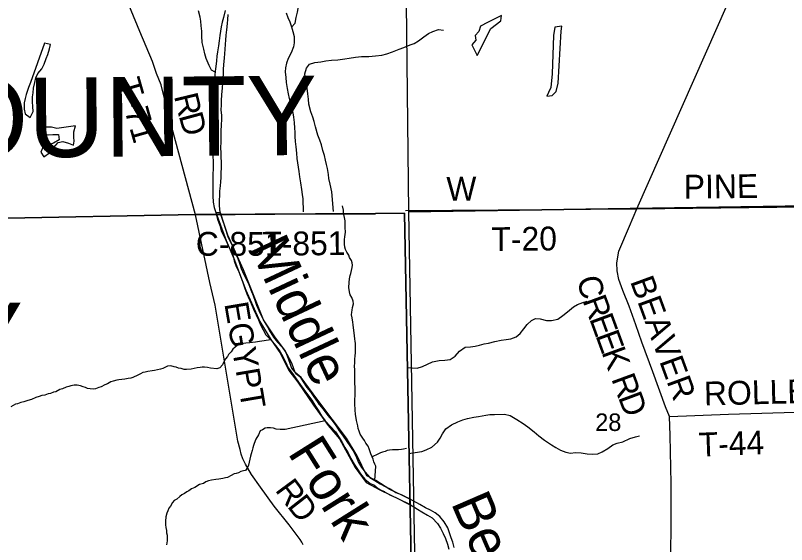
# Model space of a CAD drawing. Extents: x 0 to 34, y 0 to 22.
# Drawn here: x 6.418 to 8.257, y 18.489 to 19.751 of the extents above; entities that cross this region are included whole.
import ezdxf

# ---------------------------------------------------------------- set-up
doc = ezdxf.new("R2010")
doc.units = 0
for name, color, linetype in [('GM_X_County_Road', 7, 'Continuous'), ('GM_X_County_Road_Text', 7, 'Continuous'), ('GM_X_County_Text', 7, 'Continuous'), ('GM_X_Minor_Lake', 7, 'Continuous'), ('GM_X_Minor_River', 7, 'Continuous'), ('GM_X_Minor_River_Text', 7, 'Continuous'), ('GM_X_Rail_Line', 7, 'Continuous'), ('GM_X_Section', 7, 'Continuous'), ('GM_X_Section_Text', 7, 'Continuous'), ('GM_X_Township', 7, 'Continuous'), ('GM_X_Township_Road', 7, 'Continuous'), ('GM_X_Township_Road_Text', 7, 'Continuous'), ('SH_Cut_Line', 7, 'Continuous')]:
    doc.layers.add(name, color=color, linetype=linetype)

msp = doc.modelspace()

# ---------------------------------------------------------------- linework, layer by layer
at = {"layer": 'GM_X_County_Road'}
for p, q in [((6.847, 19.2754), (7.0368, 19.2765)), ((7.0368, 19.2765), (7.2765, 19.2778))]:
    msp.add_line(p, q, dxfattribs=at)
for points in [[(7.8996, 19.2895), (8.1438, 19.8412), (8.341, 20.2911)], [(7.9334, 18.3364), (7.945, 18.3644), (7.9586, 18.3875), (7.9674, 18.4013), (7.9744, 18.4125), (7.9791, 18.424), (7.9807, 18.4411), (7.9811, 18.4735), (7.9819, 18.5282), (7.982, 18.6343), (7.9789, 18.749), (7.9779, 18.7942), (7.9683, 18.8172), (7.9381, 18.901), (7.9119, 18.9716), (7.8977, 19.0131), (7.8816, 19.0572), (7.8668, 19.095), (7.8571, 19.1206), (7.8525, 19.1418), (7.8517, 19.1604), (7.8572, 19.1887), (7.8822, 19.2477), (7.8996, 19.2895)]]:
    msp.add_lwpolyline(points, dxfattribs=at)
at = {"layer": 'GM_X_Minor_Lake'}
for points in [[(7.5194, 19.6553), (7.5513, 19.7196), (7.5757, 19.7379), (7.577, 19.7504), (7.5435, 19.7339), (7.5269, 19.7253), (7.5226, 19.7127), (7.5144, 19.7027), (7.5161, 19.692), (7.5113, 19.6859), (7.506, 19.6805)], [(7.7196, 19.7129), (7.7206, 19.7251), (7.7046, 19.7229), (7.7008, 19.7027), (7.6978, 19.6111), (7.6945, 19.5791), (7.6894, 19.5665), (7.6854, 19.5581), (7.6975, 19.5594), (7.7076, 19.5695), (7.7122, 19.5889)], [(7.7122, 19.5889), (7.7196, 19.7129)], [(6.4541, 19.591), (6.4493, 19.5787), (6.4435, 19.5623), (6.4414, 19.5528), (6.4389, 19.5425), (6.4384, 19.5269), (6.4413, 19.5159), (6.4528, 19.507), (6.4602, 19.5216), (6.4596, 19.5337), (6.4586, 19.5443), (6.4588, 19.5565), (6.4598, 19.566), (6.4608, 19.577), (6.4639, 19.5908), (6.4668, 19.6018), (6.4716, 19.6125), (6.4805, 19.6237), (6.4864, 19.6348), (6.4915, 19.6482), (6.4955, 19.6578), (6.4994, 19.6708), (6.5012, 19.681), (6.4874, 19.6846)], [(6.4874, 19.6846), (6.4541, 19.591)], [(7.506, 19.6805), (7.5194, 19.6553)], [(6.517, 19.4807), (6.5037, 19.4839), (6.4904, 19.4844), (6.4783, 19.4797), (6.4823, 19.468), (6.4968, 19.4659), (6.5074, 19.4669), (6.5203, 19.4671), (6.522, 19.4542), (6.5085, 19.4464), (6.4953, 19.4412), (6.4825, 19.4338), (6.4785, 19.4242), (6.4859, 19.4137), (6.499, 19.4227), (6.5087, 19.4353), (6.5195, 19.4473), (6.5312, 19.4502), (6.5442, 19.4458), (6.5564, 19.4415), (6.5581, 19.451), (6.5568, 19.4605), (6.5574, 19.4734), (6.561, 19.4871)], [(6.561, 19.4871), (6.517, 19.4807)]]:
    msp.add_lwpolyline(points, dxfattribs=at)
at = {"layer": 'GM_X_Minor_River'}
for p, q in [((6.8961, 19.281), (6.9064, 19.281)), ((7.3573, 18.5978), (7.3576, 18.5848))]:
    msp.add_line(p, q, dxfattribs=at)
for points in [[(7.0761, 19.7229), (7.0846, 19.732), (7.0874, 19.7461), (7.0902, 19.7583), (7.093, 19.7721), (7.0951, 19.7839), (7.0968, 19.7972), (7.0977, 19.8067), (7.0987, 19.8185), (7.1, 19.8296), (7.1013, 19.8414), (7.1037, 19.8562), (7.1054, 19.868), (7.1079, 19.8817), (7.1096, 19.8913)], [(6.8942, 19.6155), (6.8852, 19.6205), (6.8801, 19.631), (6.873, 19.648), (6.8698, 19.6594), (6.8669, 19.67), (6.8636, 19.6859), (6.8626, 19.7014), (6.8624, 19.7128), (6.8611, 19.7257), (6.8597, 19.7367), (6.8581, 19.7466), (6.8544, 19.7617)], [(6.9064, 19.281), (6.9043, 19.2975), (6.9048, 19.3093), (6.9054, 19.3218), (6.9056, 19.3317), (6.9069, 19.3439), (6.9079, 19.3538), (6.9085, 19.3644), (6.9087, 19.3751), (6.9096, 19.3876), (6.9094, 19.4017), (6.9088, 19.4115), (6.9086, 19.4214), (6.908, 19.4362), (6.9082, 19.4476), (6.9088, 19.4602), (6.9089, 19.4754), (6.909, 19.4887), (6.9099, 19.5031), (6.9098, 19.5126), (6.9088, 19.5251), (6.909, 19.5377), (6.9096, 19.5479), (6.9105, 19.5616), (6.9114, 19.5784), (6.9123, 19.5894), (6.9129, 19.6008), (6.9138, 19.6118), (6.9144, 19.6221), (6.9146, 19.6339), (6.9162, 19.6491), (6.9172, 19.6601), (6.9178, 19.6697), (6.9191, 19.6818), (6.9197, 19.6921), (6.9203, 19.7039), (6.922, 19.7164), (6.9236, 19.7317), (6.9242, 19.7412), (6.9251, 19.7526)], [(6.9178, 19.7624), (6.9139, 19.7459), (6.911, 19.7345)], [(7.0636, 19.7568), (7.0676, 19.7458), (7.072, 19.7353), (7.076, 19.7232), (7.0796, 19.7126), (7.0824, 19.7005), (7.0823, 19.6853), (7.0809, 19.6758), (7.0755, 19.6616), (7.0685, 19.6482), (7.0645, 19.6371), (7.062, 19.6257), (7.0614, 19.6162), (7.0624, 19.6029), (7.0638, 19.5904), (7.0663, 19.5767), (7.0684, 19.5639), (7.0705, 19.5525), (7.0737, 19.5396), (7.0765, 19.5294), (7.0794, 19.5184), (7.0811, 19.5082), (7.0824, 19.4953), (7.0834, 19.482), (7.084, 19.4722), (7.0841, 19.4623), (7.0851, 19.4498), (7.0864, 19.4373), (7.0878, 19.4225), (7.0892, 19.4092), (7.0905, 19.3993), (7.0918, 19.3891), (7.0935, 19.3785), (7.0956, 19.366), (7.0977, 19.3516), (7.0999, 19.3353), (7.1016, 19.3235), (7.1033, 19.3133), (7.104, 19.2826)], [(6.911, 19.7345), (6.9089, 19.7238), (6.9055, 19.7025), (6.9034, 19.6899), (6.9021, 19.6781), (6.8997, 19.664), (6.8983, 19.6538), (6.897, 19.6423), (6.8957, 19.629), (6.8944, 19.6176), (6.8934, 19.6081), (6.894, 19.5944), (6.8961, 19.5793), (6.896, 19.5644), (6.8958, 19.5549), (6.8953, 19.5397), (6.8951, 19.5257), (6.8942, 19.5116), (6.892, 19.4876), (6.8914, 19.4747), (6.8913, 19.4606), (6.8911, 19.4504), (6.8905, 19.439), (6.8896, 19.4279), (6.889, 19.4139), (6.8896, 19.4032), (6.8891, 19.3858), (6.889, 19.3713), (6.8889, 19.3565), (6.889, 19.3459), (6.8888, 19.3356), (6.8887, 19.3208), (6.8897, 19.3056), (6.8922, 19.2924), (6.8961, 19.281)], [(7.1767, 19.2827), (7.1721, 19.3296), (7.1684, 19.3482), (7.1655, 19.3618), (7.1646, 19.3713), (7.1621, 19.3857), (7.16, 19.3955), (7.1572, 19.4054), (7.1547, 19.4167), (7.1511, 19.4288), (7.1475, 19.4417), (7.1435, 19.453), (7.1391, 19.4651), (7.1338, 19.4852), (7.1306, 19.498), (7.1274, 19.5078), (7.1222, 19.5211), (7.1178, 19.5388), (7.1164, 19.551), (7.1155, 19.5639), (7.1137, 19.5771), (7.112, 19.5881), (7.1099, 19.598), (7.1082, 19.6116), (7.1118, 19.6246), (7.1188, 19.6342), (7.1317, 19.6386), (7.1464, 19.6404), (7.1582, 19.6421), (7.1718, 19.6442), (7.187, 19.6452), (7.2033, 19.6474), (7.2135, 19.6487), (7.229, 19.6508), (7.243, 19.6526), (7.2605, 19.6529), (7.2768, 19.6543), (7.292, 19.6561), (7.3033, 19.6593), (7.3173, 19.6637), (7.3327, 19.67), (7.344, 19.674), (7.3591, 19.6803), (7.3689, 19.6839), (7.3791, 19.6902), (7.3915, 19.6999), (7.4031, 19.7073), (7.4129, 19.7124), (7.4272, 19.7172), (7.4386, 19.7158)], [(7.2753, 18.6418), (7.2771, 18.6754), (7.2751, 18.6803), (7.2723, 18.6863), (7.271, 18.6924), (7.269, 18.6977), (7.2658, 18.7052), (7.2634, 18.712), (7.2618, 18.7173), (7.259, 18.7233), (7.2532, 18.7308), (7.25, 18.7372), (7.2461, 18.7421), (7.2434, 18.7469), (7.2403, 18.7518), (7.2375, 18.759), (7.2354, 18.7654), (7.2342, 18.7715), (7.2325, 18.7779), (7.2316, 18.7847), (7.2286, 18.7999), (7.2277, 18.8094), (7.2274, 18.8253), (7.2276, 18.8303), (7.2275, 18.8356), (7.2277, 18.8432), (7.2283, 18.852), (7.2282, 18.8581), (7.2281, 18.8634), (7.2275, 18.874), (7.2274, 18.8797), (7.2269, 18.8847), (7.2271, 18.89), (7.2274, 18.8984), (7.2272, 18.9048), (7.2266, 18.9151), (7.2269, 18.9215), (7.2274, 18.9318), (7.228, 18.9379), (7.2286, 18.9467), (7.2288, 18.9554), (7.2285, 18.9684), (7.2281, 18.9737), (7.2272, 18.9786), (7.2266, 18.9877), (7.2249, 18.9995), (7.2231, 19.0124), (7.2226, 19.0188), (7.2208, 19.0298), (7.2196, 19.0363), (7.2198, 19.0431), (7.2208, 19.0481), (7.2218, 19.0542), (7.2243, 19.0626), (7.2234, 19.0694), (7.2198, 19.0777), (7.2163, 19.0845), (7.2142, 19.0913), (7.2133, 19.1019), (7.2138, 19.1141), (7.2147, 19.1221), (7.2165, 19.1301), (7.2179, 19.1351), (7.221, 19.1496), (7.2216, 19.1554), (7.2211, 19.1607), (7.2191, 19.166), (7.2148, 19.1735), (7.2128, 19.1788), (7.2085, 19.1859), (7.2053, 19.1927), (7.2037, 19.198), (7.2024, 19.2055), (7.2029, 19.2166), (7.2035, 19.2227), (7.2046, 19.228), (7.2048, 19.2334), (7.2046, 19.2451), (7.2041, 19.2508), (7.2044, 19.2558), (7.2039, 19.2607), (7.203, 19.2687), (7.2005, 19.2789), (7.1999, 19.2861), (7.1982, 19.2964)], [(6.8961, 19.281), (6.9004, 19.2621), (6.9051, 19.2493), (6.9087, 19.2372), (6.9134, 19.2274), (6.9197, 19.215), (6.9252, 19.2022), (6.9311, 19.1897), (6.937, 19.1765), (6.9394, 19.1652), (6.9446, 19.1516), (6.9505, 19.1388), (6.9556, 19.1267), (6.9604, 19.1135), (6.9647, 19.0995), (6.9695, 19.0867), (6.9797, 19.0637), (6.986, 19.0501), (6.9919, 19.0366), (6.9978, 19.0245), (7.0025, 19.0128), (7.0084, 19.0008), (7.0154, 18.9887), (7.0266, 18.9771), (7.039, 18.9625), (7.0483, 18.9498), (7.0553, 18.937), (7.0624, 18.9227), (7.0679, 18.9106), (7.0783, 18.8967), (7.0876, 18.8836), (7.0973, 18.8708), (7.1058, 18.8588), (7.1147, 18.8464), (7.1244, 18.8333), (7.1315, 18.8213), (7.1396, 18.8093), (7.1474, 18.7957), (7.1567, 18.7841), (7.181, 18.7575), (7.1899, 18.7444), (7.1973, 18.732), (7.2032, 18.7199), (7.211, 18.7075), (7.218, 18.6936), (7.2254, 18.6808), (7.2336, 18.6684), (7.241, 18.6575), (7.251, 18.6444), (7.2637, 18.6347), (7.2729, 18.6312)], [(6.8961, 19.281), (6.9202, 19.2136), (6.939, 19.1708), (6.967, 19.0958), (7.0004, 19.0208), (7.0272, 18.9779), (7.0499, 18.9444), (7.07, 18.9042), (7.0914, 18.8761), (7.1288, 18.8212), (7.1636, 18.773), (7.1904, 18.7408), (7.2278, 18.6725), (7.2546, 18.6364), (7.2867, 18.6189), (7.3576, 18.5848)], [(6.9064, 19.281), (6.9137, 19.2559), (6.9173, 19.2457), (6.9249, 19.2208), (6.9378, 19.1959), (6.9422, 19.1834), (6.9481, 19.171), (6.9524, 19.1601), (6.9564, 19.1472), (6.9619, 19.1348), (6.9682, 19.1216), (6.9741, 19.1088), (6.9796, 19.0964), (6.9847, 19.0831), (6.9895, 19.0696), (6.9931, 19.0597), (6.9986, 19.0469), (7.0049, 19.0337), (7.0107, 19.0205), (7.0189, 19.0078), (7.0252, 18.9957), (7.0333, 18.9837), (7.0426, 18.9717), (7.0538, 18.9594), (7.0631, 18.947), (7.0683, 18.9326), (7.073, 18.919), (7.0766, 18.9092), (7.0867, 18.8965), (7.0962, 18.8894), (7.1044, 18.877), (7.113, 18.8631), (7.1215, 18.853), (7.1292, 18.8414), (7.1378, 18.8301), (7.1416, 18.8233)], [(7.3573, 18.5978), (7.3108, 18.6203), (7.2773, 18.6417), (7.2559, 18.6524), (7.2332, 18.7006), (7.2078, 18.7422), (7.1369, 18.8359), (7.0994, 18.8868), (7.0847, 18.8989), (7.0767, 18.9216), (7.0606, 18.9524), (7.0379, 18.9819), (7.0098, 19.0248), (6.9617, 19.144), (6.9243, 19.227), (6.9064, 19.281)], [(7.3517, 18.9109), (7.3758, 18.9094), (7.3886, 18.9131), (7.4003, 18.9186), (7.4127, 18.9249), (7.4286, 18.9278), (7.4423, 18.9284), (7.4544, 18.9301), (7.4668, 18.9379), (7.4772, 18.9499), (7.4903, 18.9592), (7.5028, 18.9605), (7.5142, 18.9622), (7.5244, 18.9643), (7.5358, 18.9672), (7.546, 18.9692), (7.5611, 18.9733), (7.5759, 18.9762), (7.5884, 18.9779), (7.5997, 18.9796), (7.6122, 18.984), (7.6219, 18.9918), (7.6305, 19.0033), (7.6386, 19.0137), (7.6483, 19.023), (7.6585, 19.0277), (7.6692, 19.0271), (7.6844, 19.0232), (7.6962, 19.0234), (7.7113, 19.0263), (7.7233, 19.0348), (7.7342, 19.0441), (7.7484, 19.0558), (7.7582, 19.0612), (7.7714, 19.0664), (7.7812, 19.0696)], [(7.0266, 18.9771), (7, 18.9733), (6.9906, 18.9715), (6.983, 18.9706), (6.977, 18.9697), (6.9672, 18.9691), (6.9517, 18.9669), (6.9468, 18.9637), (6.9416, 18.9594), (6.936, 18.9544), (6.932, 18.9486), (6.9264, 18.942), (6.9235, 18.937), (6.9191, 18.9319), (6.9151, 18.9246), (6.9118, 18.9173), (6.9051, 18.9103), (6.8984, 18.9075), (6.8828, 18.9094), (6.876, 18.9108), (6.8684, 18.9118), (6.8631, 18.9117), (6.8581, 18.9112), (6.8513, 18.9103), (6.837, 18.9073), (6.8261, 18.9063), (6.8204, 18.9062), (6.8131, 18.9083), (6.8071, 18.9093), (6.8013, 18.9115), (6.7964, 18.9125), (6.7884, 18.9146), (6.7804, 18.914), (6.7696, 18.9089), (6.7639, 18.9072), (6.7564, 18.9055), (6.7492, 18.9039), (6.7439, 18.903), (6.7337, 18.9016), (6.727, 18.8996), (6.7217, 18.8987), (6.7164, 18.8959), (6.71, 18.8931), (6.698, 18.8871), (6.6928, 18.8859), (6.6867, 18.8846), (6.6784, 18.8833), (6.6648, 18.8815), (6.6595, 18.8806), (6.6513, 18.8781), (6.6456, 18.8765), (6.6378, 18.8717), (6.631, 18.8697), (6.6224, 18.8646), (6.6171, 18.8633), (6.6085, 18.8605), (6.6032, 18.8596), (6.5963, 18.8598), (6.5899, 18.8612), (6.5849, 18.8637), (6.5792, 18.8651), (6.5731, 18.8673), (6.5651, 18.869), (6.5583, 18.8689), (6.5503, 18.8676), (6.5455, 18.8659), (6.5387, 18.8643), (6.53, 18.8603), (6.5236, 18.8582), (6.5143, 18.8531), (6.5086, 18.8518), (6.5015, 18.8486), (6.4958, 18.8481), (6.4883, 18.8453), (6.4808, 18.8444), (6.4744, 18.8415), (6.4668, 18.8395), (6.4563, 18.8343), (6.4473, 18.8322), (6.4379, 18.829), (6.4304, 18.8273), (6.4228, 18.8244), (6.4179, 18.8232), (6.4067, 18.8172)], [(7.1416, 18.8233), (7.144, 18.8215), (7.154, 18.8087), (7.1626, 18.7967), (7.1734, 18.7844), (7.1823, 18.7727), (7.1901, 18.76), (7.1994, 18.7476), (7.2083, 18.7348), (7.2168, 18.722), (7.225, 18.71), (7.2309, 18.6965), (7.236, 18.6844), (7.2434, 18.6727), (7.2523, 18.6611), (7.2631, 18.6488), (7.2753, 18.6418), (7.288, 18.6336), (7.2995, 18.6273), (7.3128, 18.6207), (7.3251, 18.6126), (7.3377, 18.6078), (7.3573, 18.5978)], [(7.3554, 18.7062), (7.3874, 18.7109), (7.3976, 18.7145), (7.4112, 18.7208), (7.4242, 18.7328), (7.4309, 18.7424), (7.4365, 18.7524), (7.4446, 18.7651), (7.4581, 18.7744), (7.4732, 18.7815), (7.4845, 18.7859), (7.4958, 18.7891), (7.5113, 18.7924), (7.5223, 18.7941), (7.5397, 18.797), (7.5496, 18.7987), (7.5606, 18.7993), (7.5841, 18.7997), (7.5974, 18.7965), (7.6135, 18.7872), (7.6285, 18.7772), (7.64, 18.7694), (7.655, 18.7572), (7.6658, 18.7478), (7.6797, 18.7374), (7.6962, 18.7267), (7.7065, 18.7204), (7.7176, 18.7138), (7.7303, 18.709), (7.7413, 18.7069), (7.7534, 18.7083), (7.7671, 18.7077), (7.7812, 18.7053), (7.7949, 18.7044), (7.8066, 18.7054), (7.8172, 18.7101), (7.8303, 18.7179), (7.8427, 18.7268), (7.8525, 18.7308), (7.8661, 18.7337), (7.8831, 18.7419), (7.8963, 18.746), (7.9065, 18.748)], [(7.1567, 18.7841), (7.0608, 18.7635), (7.0495, 18.7628), (7.04, 18.7642), (7.0331, 18.7663), (7.0259, 18.7669), (7.018, 18.7671), (7.0131, 18.7666), (7.0071, 18.7627), (7.0018, 18.7599), (6.9979, 18.7503), (6.9913, 18.7403), (6.9873, 18.7299), (6.9859, 18.7249), (6.9841, 18.7192), (6.9823, 18.7131), (6.9802, 18.705), (6.9785, 18.6997), (6.9754, 18.6851), (6.9736, 18.6783), (6.9711, 18.6725), (6.9667, 18.6652), (6.9614, 18.6643), (6.9557, 18.6627), (6.9497, 18.6599), (6.9441, 18.6578), (6.9392, 18.657), (6.9325, 18.6534), (6.9238, 18.6486), (6.9186, 18.6478), (6.9122, 18.6461), (6.9031, 18.6448), (6.8955, 18.6435), (6.8857, 18.6425), (6.8782, 18.6408), (6.8722, 18.638), (6.8662, 18.6345), (6.8572, 18.6316), (6.8455, 18.6249), (6.8377, 18.622), (6.8317, 18.617), (6.8265, 18.6142), (6.8212, 18.6103), (6.8149, 18.6075), (6.8096, 18.6032), (6.8029, 18.5973), (6.7966, 18.5941), (6.7921, 18.5891), (6.7874, 18.5806), (6.7837, 18.5752), (6.7816, 18.5695), (6.779, 18.5637), (6.7769, 18.5549), (6.7756, 18.5442), (6.7758, 18.5355), (6.7767, 18.529), (6.778, 18.5222), (6.7785, 18.5169), (6.7794, 18.5108), (6.7799, 18.5032), (6.78, 18.4972), (6.7783, 18.4884)], [(7.3508, 18.7177), (7.3433, 18.7164), (7.3384, 18.7152), (7.3312, 18.7146), (7.3232, 18.7145), (7.3168, 18.7147), (7.31, 18.7138), (7.3047, 18.7129), (7.2994, 18.7109), (7.2934, 18.7092), (7.2881, 18.7076), (7.2822, 18.7044), (7.269, 18.6977)], [(7.2729, 18.6312), (7.2828, 18.6225), (7.2919, 18.6175), (7.2983, 18.6153)], [(7.2967, 18.6153), (7.2984, 18.6141), (7.3122, 18.6067), (7.3267, 18.6001), (7.3559, 18.5848)], [(7.4645, 18.4813), (7.4609, 18.4945), (7.4569, 18.5047), (7.4525, 18.5191), (7.4489, 18.5289), (7.4407, 18.5428), (7.4298, 18.5559), (7.4191, 18.5645), (7.408, 18.5711), (7.3961, 18.5762), (7.3819, 18.5844), (7.3573, 18.5978)], [(7.3576, 18.5848), (7.3768, 18.5733), (7.3868, 18.5666), (7.4002, 18.5592), (7.4117, 18.5522), (7.4244, 18.5391), (7.4314, 18.5282), (7.4381, 18.5154), (7.4432, 18.5029), (7.448, 18.4897), (7.4513, 18.4776)]]:
    msp.add_lwpolyline(points, dxfattribs=at)
at = {"layer": 'GM_X_Rail_Line'}
msp.add_lwpolyline([(5.5102, 20.2613), (5.523, 19.2739), (5.5231, 19.2652), (5.5475, 19.2638), (5.6176, 19.2598), (5.6417, 19.2587), (5.7517, 19.2562), (5.8416, 19.2572), (5.9232, 19.2589), (5.975, 19.26), (6.1325, 19.2626), (6.1415, 19.2628), (6.1868, 19.2635), (6.2112, 19.2639), (6.3582, 19.2663), (6.8468, 19.2759), (7.2763, 19.2784), (7.3458, 19.2789), (7.3701, 17.9909), (7.3831, 17.2974), (7.46, 17.2982), (7.4754, 17.3006), (8.2882, 17.3064)], dxfattribs=at)
at = {"layer": 'GM_X_Section'}
for points in [[(7.3448, 20.2776), (8.3505, 20.2885), (8.3591, 19.2972), (7.3562, 19.2826)], [(7.3562, 19.2826), (8.3591, 19.2972), (8.3698, 18.3026), (7.3737, 18.2882)]]:
    msp.add_lwpolyline(points, close=True, dxfattribs=at)
at = {"layer": 'GM_X_Township'}
msp.add_lwpolyline([(6.3582, 19.2663), (6.8468, 19.2759), (7.2763, 19.2784), (7.3458, 19.2789), (7.3701, 17.9909), (7.3831, 17.2974), (7.46, 17.2982), (7.4754, 17.3006), (7.4757, 17.0495), (7.4723, 16.4951), (7.4818, 15.827), (7.482, 15.8179), (7.4834, 15.2992)], dxfattribs=at)
at = {"layer": 'GM_X_Township_Road'}
for p, q in [((7.8996, 19.2895), (8.9, 19.302)), ((6.847, 19.2754), (7.0368, 19.2765)), ((7.0368, 19.2765), (7.2765, 19.2778)), ((7.3479, 19.2855), (7.8996, 19.2895))]:
    msp.add_line(p, q, dxfattribs=at)
for points in [[(6.847, 19.2754), (6.7841, 19.5108), (6.7657, 19.5851), (6.7546, 19.6119), (6.7446, 19.6406), (6.7149, 19.7124), (6.6581, 19.8503), (6.6219, 19.9631), (6.6196, 19.9836), (6.6226, 19.9897), (6.6271, 19.9947), (6.6338, 20.0013), (6.6398, 20.0094), (6.6388, 20.0212), (6.6367, 20.0561), (6.6366, 20.0633), (6.6357, 20.1352), (6.5689, 20.1357)], [(7.1044, 18.4881), (7.1009, 18.4943), (7.097, 18.5005), (7.0707, 18.5354), (7.0352, 18.5803), (7.0023, 18.6253), (6.9807, 18.656), (6.9667, 18.6805), (6.9604, 18.6929), (6.9564, 18.7042), (6.9536, 18.7155), (6.9484, 18.7352), (6.9064, 18.988), (6.8943, 19.0593), (6.8811, 19.1138), (6.847, 19.2754)], [(7.9779, 18.7942), (8.1182, 18.7998), (8.2774, 18.8045), (8.3451, 18.8044), (8.3694, 18.8075), (8.4051, 18.8098), (8.435, 18.8149), (8.4822, 18.8129), (8.8446, 18.8126), (8.9, 18.8124)]]:
    msp.add_lwpolyline(points, dxfattribs=at)
at = {"layer": 'SH_Cut_Line'}
for points in [[(6.3582, 19.2663), (6.8468, 19.2759), (7.2763, 19.2784), (7.3458, 19.2789), (7.3701, 17.9909), (7.3831, 17.2974), (7.46, 17.2982), (7.4754, 17.3006), (8.2882, 17.3064)], [(8.2882, 17.3064), (7.4754, 17.3006), (7.46, 17.2982), (7.3831, 17.2974), (7.3701, 17.9909), (7.3458, 19.2789), (7.2763, 19.2784), (6.8468, 19.2759), (6.3582, 19.2663)]]:
    msp.add_lwpolyline(points, dxfattribs=at)

# ---------------------------------------------------------------- texts
at = {"layer": 'GM_X_County_Road_Text'}
for s, height, rotation, p in [('C-851', 0.05682, 0, (6.8481, 19.1775)), ('C', 0.0568, 284.2843, (7.7563, 19.1226)), ('BEAVER', 0.05682, 290.099, (7.8831, 19.1167)), ('R', 0.0568, 290.2235, (7.7697, 19.0712)), ('E', 0.0568, 290.0981, (7.7858, 19.0275)), ('E', 0.0568, 290.1131, (7.8005, 18.9875)), ('K', 0.0568, 290.1154, (7.8151, 18.9476)), ('R', 0.0568, 290.1534, (7.8383, 18.8842)), ('D', 0.0568, 290.4234, (7.8545, 18.8401))]:
    msp.add_text(s, height=height, rotation=rotation, dxfattribs=at).set_placement(p)
at = {"layer": 'GM_X_County_Text'}
for s, rotation, p in [('MAHONING COUNTY', 0.475, (4.6057, 19.3971)), ('COLUMBIANA COUNTY', 0.8253, (3.6247, 18.8361))]:
    msp.add_text(s, height=0.189394, rotation=rotation, dxfattribs=at).set_placement(p)
at = {"layer": 'GM_X_Minor_River_Text'}
for s, height, rotation, p in [('Middle', 0.09474, 295.1496, (6.9744, 19.1972)), ('Fork', 0.09473, 302.15, (7.0656, 18.7076)), ('Beaver', 0.09473, 293.3976, (7.4557, 18.5883))]:
    msp.add_text(s, height=height, rotation=rotation, dxfattribs=at).set_placement(p)
at = {"layer": 'GM_X_Section_Text'}
msp.add_text('28', height=0.04186, rotation=0, dxfattribs=at).set_placement((7.8006, 18.7596))
at = {"layer": 'GM_X_Township_Road_Text'}
for s, height, rotation, p in [('T-71', 0.05682, 285.9035, (6.6582, 19.5927)), ('R', 0.0568, 283.5161, (6.7957, 19.5586)), ('D', 0.0568, 285.173, (6.807, 19.5116)), ('W', 0.0568, 0.7248, (7.4461, 19.3086)), ('PINE', 0.05682, 0.619, (8.012, 19.3136)), ('T-20', 0.05682, 0.7076, (7.5534, 19.1885)), ('T-851', 0.05682, 0.4511, (7.0068, 19.1777)), ('EGYPT', 0.05682, 279.6372, (6.9159, 19.0632)), ('ROLLER', 0.05682, 1.4167, (8.0606, 18.8203)), ('T-44', 0.05682, 2.1209, (8.0481, 18.6985)), ('R', 0.0568, 306.4343, (7.0356, 18.6186)), ('D', 0.0568, 308.0088, (7.0643, 18.5797))]:
    msp.add_text(s, height=height, rotation=rotation, dxfattribs=at).set_placement(p)

doc.saveas('drawing.dxf')
